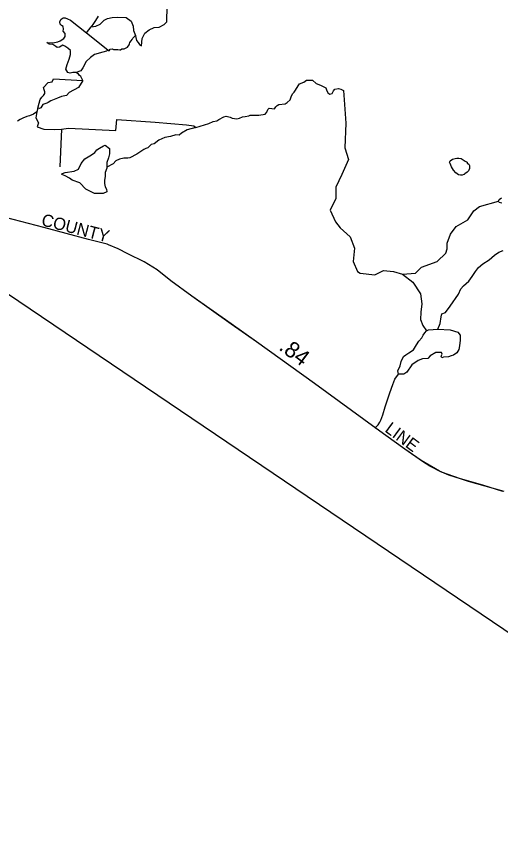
# Model space of a CAD drawing. Extents: x 2082433 to 2279600, y 546599 to 755198.
# Drawn here: x 2093272 to 2097030, y 632912 to 639289 of the extents above; entities that cross this region are included whole.
import ezdxf

# ---------------------------------------------------------------- set-up
doc = ezdxf.new("R2010")
doc.units = 0
for name, color, linetype in [('Exist Boundary Political CountyLine', 7, 'Continuous'), ('Exist Boundary Political Fire Districts', 7, 'Continuous'), ('Exist Hydrographic Creek Single Shore', 7, 'Continuous'), ('Exist Hydrographic Pond Over 1500 Sq Ft', 7, 'Continuous'), ('Exist Hydrographic Pond Under 1500 Sq Ft', 7, 'Continuous'), ('Exist Road Secondary Mileage Hundredths English Label', 7, 'Continuous'), ('Exist Road Secondary Type 51 Label', 7, 'Continuous'), ('Map Preparation Inset Cut Line', 7, 'Continuous')]:
    doc.layers.add(name, color=color, linetype=linetype)

msp = doc.modelspace()

# ---------------------------------------------------------------- linework, layer by layer
at = {"layer": 'Exist Boundary Political CountyLine'}
msp.add_lwpolyline([(2097058.5, 635604.4), (2096782.3, 635682), (2096719.3, 635702.2), (2096629.8, 635731.7), (2096556, 635763.1), (2096413, 635845.8), (2096286, 635933.9), (2096140.8, 636039), (2096064.3, 636092.3), (2095585.3, 636441.2), (2095135.2, 636764.1), (2094938.8, 636903.5), (2094634.9, 637119.1), (2094471.7, 637238.7), (2094364, 637323.5), (2094263, 637384.8), (2094136, 637448.4), (2094063.2, 637487.2), (2093987.4, 637518.1), (2093976.1, 637522.8), (2093832.3, 637558.8), (2093485, 637653.2), (2093187.5, 637728.4)], dxfattribs=at)
at = {"layer": 'Exist Boundary Political Fire Districts'}
msp.add_lwpolyline([(2097047.2, 635603.7), (2096891.7, 635652.2), (2096719.3, 635702.3), (2096570.8, 635753.9), (2096480.4, 635801), (2096423.2, 635835.9), (2096286, 635933.9), (2096140.8, 636039), (2096064.3, 636092.4), (2095585.3, 636441.3), (2095135.2, 636764.2), (2094938.8, 636903.6), (2094634.9, 637119.1), (2094471.7, 637238.8), (2094364, 637323.6), (2094263, 637384.8), (2094136, 637448.4), (2094063.2, 637487.2), (2093987.4, 637518.2), (2093976.1, 637522.8), (2093832.3, 637558.9), (2093485, 637653.2), (2093187.5, 637728.5)], dxfattribs=at)
at = {"layer": 'Exist Hydrographic Creek Single Shore'}
for p, q in [((2093816.7, 639162.7), (2093852.5, 639207.7)), ((2093623, 638414.8), (2093609.7, 638121.7))]:
    msp.add_line(p, q, dxfattribs=at)
for points in [[(2093982.6, 639029.5), (2093992.9, 639022.3), (2094001.1, 639035.6), (2094015.4, 639037.7), (2094026.7, 639033.6), (2094060.5, 639032.5), (2094073.8, 639030.5), (2094080, 639030.5), (2094091.2, 639037.7), (2094099.4, 639037.7), (2094107.6, 639037.7), (2094118.9, 639043.8), (2094133.2, 639052), (2094147.6, 639069.4), (2094150.6, 639077.6), (2094152.7, 639085.8), (2094164, 639100.2), (2094170.1, 639111.4), (2094175.2, 639119.6), (2094184.5, 639127.8), (2094195.7, 639140.1)], [(2093789, 638791.8), (2093771.6, 638822.5), (2093758.3, 638833.8), (2093753.1, 638842), (2093734.7, 638853.3)], [(2093439.6, 638577.7), (2093429.4, 638550), (2093403.8, 638530.5), (2093373, 638517.2), (2093353.6, 638514.1), (2093321.8, 638499.8), (2093302.3, 638488.5), (2093279.8, 638477.2)], [(2093429.4, 638550), (2093423.2, 638501.8), (2093442.7, 638462.9), (2093434.5, 638432.2), (2093484.7, 638415.8), (2093566.7, 638412.7), (2093623, 638414.8)], [(2093623, 638414.8), (2093676.3, 638422.9), (2094044.1, 638404.5), (2094052.3, 638488.5), (2094348.4, 638468), (2094593.2, 638448.6), (2094649.6, 638441.4), (2094666, 638428.1)], [(2094666, 638428.1), (2094598.4, 638409.6), (2094554.3, 638385), (2094534.8, 638368.6), (2094509.2, 638370.7), (2094469.3, 638357.4), (2094424.2, 638349.2), (2094377.1, 638328.7), (2094340.2, 638301), (2094317.6, 638294.9), (2094292, 638270.3), (2094277.7, 638264.1), (2094261.3, 638255.9), (2094208, 638220.1), (2094151.7, 638191.4), (2094137.3, 638189.4), (2094106.6, 638189.4), (2094072.8, 638183.2), (2094045.1, 638168.9), (2094022.6, 638146.3), (2093974.4, 638119.7)], [(2097039.8, 637840), (2097018.8, 637847.2), (2097014.7, 637857.4), (2097020.4, 637869.7), (2097038.3, 637881)], [(2096544.5, 636862.6), (2096560.9, 636906.6), (2096570.1, 636957.9), (2096575.2, 636983.5), (2096602.9, 636991.7), (2096639.8, 637041.9), (2096702.9, 637134), (2096721.1, 637177), (2096742.9, 637198.9), (2096782.8, 637236.7), (2096810.9, 637272.6), (2096834.7, 637310.7), (2096860.3, 637342.9), (2096892.7, 637370.9), (2096942.4, 637401.1), (2096984, 637437), (2097016.2, 637461.3), (2097050.1, 637472.7)], [(2096053.5, 636095.2), (2096080.3, 636120.3), (2096092, 636142), (2096100.2, 636158.2), (2096115.8, 636198), (2096133.8, 636260.2), (2096149.4, 636308.1), (2096171.4, 636370.5), (2096195.2, 636434.2), (2096210.7, 636474.4), (2096237.1, 636513.2)]]:
    msp.add_lwpolyline(points, dxfattribs=at)
at = {"layer": 'Exist Hydrographic Pond Over 1500 Sq Ft'}
for points in [[(2093906.8, 639291.8), (2093886.3, 639257.9), (2093869.9, 639235.4), (2093852.5, 639207.7), (2093888.4, 639214.9), (2093922.2, 639229.3), (2093953.9, 639260), (2093978.5, 639274.3), (2094015.4, 639280.5), (2094060.5, 639282.5), (2094123, 639280.5), (2094161.9, 639252.8), (2094179.3, 639212.9), (2094181.4, 639179.1), (2094195.7, 639140.1), (2094198.8, 639125.8), (2094203.9, 639103.2), (2094218.3, 639086.8), (2094226.5, 639072.5), (2094243.9, 639061.2), (2094249, 639117.6), (2094268.5, 639159.6), (2094302.3, 639185.2), (2094341.2, 639202.6), (2094381.2, 639204.7), (2094420.1, 639227.2), (2094440.6, 639246.7), (2094445.7, 639491.5)], [(2094666, 638428.1), (2094766.4, 638459.8), (2094799.2, 638474.2), (2094827.9, 638479.3), (2094844.3, 638488.5), (2094881.1, 638511.1), (2094900.6, 638516.2), (2094931.3, 638509), (2094945.7, 638499.8), (2094965.2, 638497.7), (2094982.6, 638494.7), (2095005.1, 638499.8), (2095027.6, 638511.1), (2095047.1, 638513.1), (2095075.8, 638519.3), (2095087.1, 638522.3), (2095109.6, 638522.3), (2095154.7, 638522.3), (2095202.8, 638530.5), (2095216.2, 638546.9), (2095224.4, 638566.4), (2095233.6, 638577.7), (2095256.1, 638575.6), (2095275.6, 638573.6), (2095286.9, 638586.9), (2095295.1, 638598.1), (2095309.4, 638606.3), (2095357.5, 638611.5), (2095373.9, 638620.7), (2095396.5, 638643.2), (2095404.7, 638665.8), (2095415.9, 638688.3), (2095427.2, 638701.6), (2095438.5, 638716), (2095459, 638749.8), (2095470.2, 638766.2), (2095504.1, 638780.5), (2095523.5, 638793.8), (2095571.7, 638794.9), (2095599.3, 638769.2), (2095633.1, 638755.9), (2095673.1, 638735.4), (2095678.2, 638719), (2095689.5, 638696.5), (2095703.8, 638685.2), (2095722.3, 638690.4), (2095733.6, 638712.9), (2095742.8, 638724.2), (2095773.5, 638730.3), (2095789.9, 638725.2), (2095812.4, 638713.9)], [(2095812.4, 638713.9), (2095829.9, 638461.9), (2095821.7, 638269.3), (2095850.3, 638179.1), (2095797.1, 638064.4), (2095752, 637966), (2095752, 637875.8), (2095706.9, 637785.7), (2095747.9, 637695.5), (2095784.8, 637650.4), (2095862.6, 637580.8), (2095895.4, 637490.6), (2095887.2, 637388.2), (2095920, 637310.3), (2095940.5, 637298), (2096055.3, 637285.7), (2096120.8, 637318.5), (2096198.7, 637310.3), (2096268.4, 637289.8), (2096370.8, 637298), (2096415.9, 637343.1), (2096538.8, 637388.2), (2096604.4, 637453.7), (2096616.7, 637486.5), (2096616.7, 637531.6), (2096641.3, 637601.3), (2096686.4, 637658.6), (2096776.5, 637711.9), (2096821.6, 637781.6), (2096866.7, 637814.4), (2097014.7, 637857.4)], [(2096268.4, 637289.8), (2096350.3, 637228.3), (2096407.7, 637138.2), (2096420, 637060.3), (2096411.8, 636994.7), (2096407.7, 636937.4), (2096428.2, 636892.3), (2096456.4, 636850.3)]]:
    msp.add_lwpolyline(points, dxfattribs=at)
for points in [[(2093816.7, 639162.7), (2093982.6, 639029.5), (2093971.4, 639019.2), (2093943.7, 639011), (2093879.1, 638993.6), (2093847.4, 638971.1), (2093813.6, 638940.3), (2093789, 638890.1), (2093771.6, 638867.6), (2093734.7, 638853.3), (2093710.1, 638853.3), (2093689.6, 638850.2), (2093670.1, 638855.3), (2093655.8, 638880.9), (2093667.1, 638916.8), (2093680.4, 638956.7), (2093691.7, 638993.6), (2093691.7, 639024.3), (2093670.1, 639043.8), (2093647.6, 639058.2), (2093631.2, 639066.4), (2093605.6, 639050), (2093588.2, 639047.9), (2093576.9, 639055.1), (2093554.4, 639072.5), (2093526.7, 639074.6), (2093509.3, 639085.8), (2093554.4, 639083.8), (2093593.3, 639092), (2093612.8, 639100.2), (2093641.5, 639117.6), (2093649.7, 639134), (2093649.7, 639156.5), (2093636.3, 639176), (2093638.4, 639190.3), (2093636.3, 639209.8), (2093622, 639219), (2093610.7, 639230.3), (2093608.7, 639246.7), (2093615.8, 639264.1), (2093630.2, 639275.4), (2093638.4, 639277.4), (2093649.7, 639277.4), (2093669.1, 639270.2), (2093691.7, 639259)], [(2093481.6, 638737.5), (2093518.5, 638777.4), (2093549.2, 638782.6), (2093560.5, 638805.1), (2093789, 638791.8), (2093755.2, 638737.5), (2093682.4, 638699.6), (2093659.9, 638677), (2093623, 638667.8), (2093592.3, 638654.5), (2093539, 638634), (2093518.5, 638620.7), (2093507.2, 638617.6), (2093476.5, 638606.3), (2093462.2, 638580.7), (2093450.9, 638575.6), (2093439.6, 638577.7), (2093447.8, 638616.6), (2093456, 638645.3), (2093470.4, 638661.7), (2093481.6, 638676), (2093492.9, 638690.4), (2093492.9, 638703.7), (2093487.8, 638721.1)], [(2093649.7, 638077.7), (2093719.3, 638087.9), (2093753.1, 638105.3), (2093775.7, 638147.3), (2093804.4, 638184.2), (2093854.6, 638215), (2093880.2, 638234.4), (2093897.6, 638254.9), (2093917.1, 638268.2), (2093947.8, 638285.7), (2093962.1, 638290.8), (2093995.9, 638264.1), (2093993.9, 638224.2), (2093985.7, 638193.5), (2093974.4, 638156.6), (2093974.4, 638119.7), (2093974.4, 638111.5), (2093960.1, 638077.7), (2093960.1, 638050), (2093957, 638016.2), (2093957, 637993.7), (2093962.1, 637968.1), (2093970.3, 637948.6), (2093973.4, 637928.1), (2093945.7, 637914.8), (2093878.1, 637916.8), (2093810.5, 637950.6), (2093765.4, 637997.8), (2093704, 638018.3), (2093683.5, 638034.6), (2093649.7, 638052.1), (2093625.1, 638063.3), (2093629.2, 638071.5)], [(2096470.7, 636857.5), (2096544.5, 636862.6), (2096639.8, 636857.5), (2096698.2, 636840), (2096715.6, 636817.5), (2096715.6, 636778.6), (2096710.4, 636733.5), (2096705.3, 636704.8), (2096691, 636679.2), (2096665.4, 636662.8), (2096645.9, 636656.7), (2096626.4, 636648.5), (2096586.5, 636645.4), (2096575.2, 636640.3), (2096570.1, 636653.6), (2096577.3, 636670), (2096572.1, 636681.2), (2096527.1, 636682.3), (2096485, 636656.7), (2096465.6, 636637.2), (2096425.6, 636632.1), (2096389.8, 636620.8), (2096340.6, 636587), (2096301.7, 636530.6), (2096279.1, 636513.2), (2096237.1, 636513.2), (2096232, 636540.9), (2096250.4, 636577.8), (2096258.6, 636611.6), (2096276, 636650.5), (2096295.5, 636664.8), (2096318, 636679.2), (2096354.9, 636703.8), (2096377.5, 636740.7), (2096396.9, 636769.4), (2096419.5, 636797), (2096430.7, 636816.5), (2096442, 636833.9), (2096456.4, 636850.3)]]:
    msp.add_lwpolyline(points, close=True, dxfattribs=at)
at = {"layer": 'Exist Hydrographic Pond Under 1500 Sq Ft'}
msp.add_lwpolyline([(2096772, 638150.4), (2096783.7, 638142.1), (2096788, 638132.2), (2096789.8, 638128.2), (2096789.8, 638120.5), (2096789.8, 638110.4), (2096782.2, 638090.5), (2096769.9, 638080.2), (2096753.9, 638068.4), (2096748.2, 638062.4), (2096744.5, 638062.1), (2096732.4, 638058.3), (2096718.2, 638058), (2096702.5, 638060), (2096684.2, 638076.1), (2096664.1, 638097.8), (2096650.2, 638121.8), (2096638.1, 638148), (2096634.2, 638157.9), (2096639.9, 638170), (2096658.2, 638181.9), (2096677.9, 638187.8), (2096691.8, 638190.2), (2096705.7, 638190.1), (2096723.8, 638186.1), (2096740, 638176.3), (2096755.8, 638166.2), (2096772, 638158.1), (2096772, 638150.4)], dxfattribs=at)
at = {"layer": 'Map Preparation Inset Cut Line'}
msp.add_lwpolyline([(2103425.3, 630228.2), (2082433, 644416.2), (2103425.3, 662094.1)], close=True, dxfattribs=at)

# ---------------------------------------------------------------- texts
at = {"layer": 'Exist Road Secondary Mileage Hundredths English Label'}
msp.add_text('.84', height=125, rotation=323.04495, dxfattribs=at).set_placement((2095302.4, 636709.5))
at = {"layer": 'Exist Road Secondary Type 51 Label'}
for s, rotation, p in [('COUNTY', 345.52019, (2093459.6, 637669.7)), ('LINE', 323.43753, (2096125.4, 636073.7))]:
    msp.add_text(s, height=95, rotation=rotation, dxfattribs=at).set_placement(p)

doc.saveas('drawing.dxf')
